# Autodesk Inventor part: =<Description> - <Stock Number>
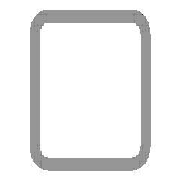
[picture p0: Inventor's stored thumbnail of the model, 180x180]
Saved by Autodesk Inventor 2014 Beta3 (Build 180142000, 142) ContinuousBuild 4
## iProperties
IsCustomPart: 1
_CCFamilyMember: 9
_CCFamilyDisplayName: ANSI AISC (Square) - Tube
_FrameMemberDoc: Frame Member File
_Version: 15.0.0
_GetPNFromCC: 1
Created: 2011-01
Part Number: =<Description> - <Stock Number>
Material: Steel, Mild
Description: Tube
Document SubType Name: Modeling
Standard: ANSI
Designer: Beta-8540w
Standards Organization: ANSI
Language: en-US
Size Designation: 3x3x3/16
Categories: <MemberInstance><Categories><Category DisplayName="Structural Shapes" InternalName="089c4875-fa83-4c05-b084-43b9cc11f5ed" Mnemonic="GRDR"><CategoryParameter Dis
Stock Number: 3x3x3/16
Density: 7.86 g/cm^3
Appearance: Steel
G_L: 58.775 in
G_W: 3.000 in
G_H: 3.000 in
+AE3CA65D-4403-45DE-BD14-7280831DFD21+CUTDETAIL1: Cut
Author: Beta-8540w
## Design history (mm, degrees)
node "Start plane"
node "End plane"
sketch "Sketch"
  geometry: L1 (-38.1, -28.575)-(-38.1, 28.575); L2 (-28.575, 38.1)-(28.575, 38.1); L3 (38.1, 28.575)-(38.1, -28.575); L4 (28.575, -38.1)-(-28.575, -38.1); L5 (-28.575, 33.337)-(28.575, 33.338); L6 (33.338, 28.575)-(33.338, -28.575); L7 (28.575, -33.337)-(-28.575, -33.338); L8 (-33.338, -28.575)-(-33.338, 28.575); L9 (0, 56.102)-(0, -56.102) reference; L10 (-56.102, 0)-(56.102, 0) reference; A1 r 9.525 centre (-28.575, -28.575) between (-38.1, -28.575) and (-28.575, -38.1); A2 r 9.525 centre (-28.575, 28.575) between (-28.575, 38.1) and (-38.1, 28.575); A3 r 9.525 centre (28.575, 28.575) between (38.1, 28.575) and (28.575, 38.1); A4 r 9.525 centre (28.575, -28.575) between (28.575, -38.1) and (38.1, -28.575); A5 r 4.763 centre (-28.575, 28.575) between (-28.575, 33.337) and (-33.338, 28.575); A6 r 4.763 centre (28.575, 28.575) between (33.338, 28.575) and (28.575, 33.338); A7 r 4.763 centre (28.575, -28.575) between (28.575, -33.337) and (33.338, -28.575); A8 r 4.763 centre (-28.575, -28.575) between (-33.338, -28.575) and (-28.575, -33.338)
  constraints: 16 end point, 16 point on circle, 8 centre point, 8 tangent, 4 parallel, 3 equal radius, 2 perpendicular, 7 other
  dimensions: "d10" = 76.2 distance between parallel lines of L2 L4 (= G_H); "d11" = 76.2 distance between parallel lines of L1 L3 (= G_W); "d12" = 4.7625 distance between parallel lines of L3 L6 (= G_T); "d15" = 38.1 distance between parallel lines of L2 L10 (= 0.5 x d10); "d16" = 38.1 distance between parallel lines of L9 L3 (= 0.5 x d11); "d17" = 9.525 radius of A1 (= G_IR)
extrude "Body" new body sketch "Sketch" stored distance "d3" = 1492.89148 (= G_L); taper "d4" = 0 deg
node "Driven Length"
  sketch "Sketch3"
    geometry: L1 (0, 0)-(10, 0) reference
    constraints: 2 end point, 1 horizontal
  workplane "Work Plane3"
  sketch "Sketch4"
    geometry: L1 (-2, 0)-(12, 0) reference; L2 (-2, 1492.891)-(12, 1492.891) reference
    dimensions: "d19" = 1492.89148 distance between parallel lines of L1 L2 (derived)
workplane "Work Plane4"
split "Split1"
body "Solid1"
other parameters: "G_W" = 76.2 [user parameter; used in 1 equation term], "G_H" = 76.2 [user parameter; used in 1 equation term], "G_T" = 4.7625 [user parameter; used in 1 equation term], "G_IR" = 9.525 [user parameter; used in 1 equation term], "G_L" = 1492.89148 (= d19) [user parameter; used in 1 equation term], "G_OFFSET_START" = 0 [user parameter; used in 1 equation term], "G_OFFSET_END" = -31.10852 [user parameter; used in 1 equation term], "d13" = 0 (computed from G_OFFSET_START), "d14" = 1492.89148 (= G_OFFSET_END + B_L), "B_L" = 1524 [user parameter; used in 1 equation term], "d18" = 90 deg
